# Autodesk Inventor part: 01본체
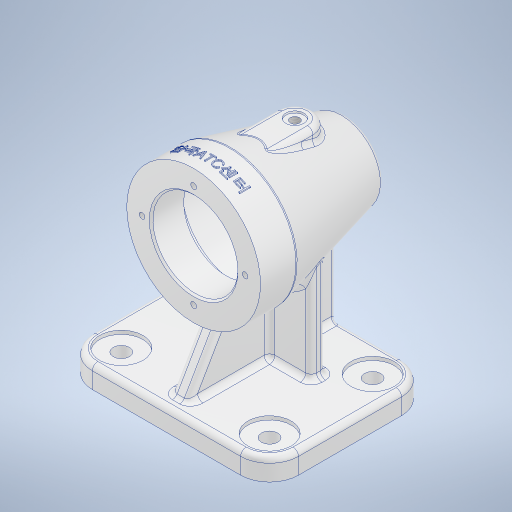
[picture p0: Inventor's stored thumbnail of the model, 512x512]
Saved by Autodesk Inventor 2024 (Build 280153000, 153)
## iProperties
Created: 2024-12
Part Number: 01본체
Material: 알루미늄 6061
Document SubType Name: Modeling
Designer: user
Density: 2.7 g/cm^3
Appearance: 알루미늄 - 평지
Mass: 740.131 g
Surface Area: 668.51 cm^2
Volume: 274.123 cm^3
Author: user
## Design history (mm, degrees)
sketch "스케치2"
  geometry: L1 (0, 56)-(0, -28); L2 (0, -28)-(21, -28); L3 (37, 36)-(37, 56); L4 (37, 56)-(0, 56); L5 (37, 36)-(21, -28); 1 further point
  constraints: 10 end point, 2 perpendicular, 1 horizontal, 1 vertical, 1 vertical alignment
  dimensions: "d5" = 84 distance of L1.start L1.end; "d7" = 20 distance of L3.start L3.end; "d8" = 42 diameter of L2.end L1; "d9" = 74 diameter of L3 L1; "d38" = 56 distance of point (0, 0) L1.start
revolve "회전1" sketch "스케치2" stored, may be unused: angle "d23" = 90 deg
fillet "모깎기1" dims "d24" = 3
node "작업 평면1"
sketch "스케치3"
  geometry: L1 (57, -18)-(-57, -18); L2 (-57, -18)-(-57, 71); L3 (-57, 71)-(57, 71); L4 (57, 71)-(57, -18); L5 (57, -18)-(-57, 71); L6 (-57, -18)-(57, 71); 2 further points
  constraints: 12 end point, 2 midpoint, 2 parallel, 1 horizontal, 1 perpendicular, 1 vertical alignment
  dimensions: "d29" = 71 distance from line of point (0, 0) L3; "d30" = 89 distance of L1.end L2.end; "d31" = 114 distance of L1.start L1.end
extrude "돌출2" join sketch "스케치3" distance "d32" = 12; taper "d33" = 0 deg
fillet "모깎기2" dims "d34" = 16
sketch "스케치4"
  geometry: L1 (41, 18)-(-41, 18) reference; L2 (-28, -11)-(28, -11); L3 (28, -11)-(28, -19); L4 (28, -19)-(-28, -19); L5 (-28, -19)-(-28, -11); L6 (-28, -11)-(28, -19); L7 (28, -11)-(-28, -19); 2 further points
  constraints: 12 end point, 2 midpoint, 2 parallel, 1 horizontal, 1 perpendicular, 1 vertical alignment
  dimensions: "d35" = 8 distance of L2.end L3.end; "d36" = 56 distance of L2.start L2.end; "d37" = 29 distance between parallel lines of L1 L2
extrude "돌출3" join sketch "스케치4" stored distance "d39" = 12; taper "d40" = 0 deg
sketch "스케치5"
  geometry: L1 (36.91, 35.642)-(21.568, -25.728) reference; L2 (18.658, -28)-(-18.658, -28) reference; L3 (-21.568, -25.728)-(-30.75, 11) reference; L4 (-30.75, 11)-(-70, 11) reference; L5 (-70, 11)-(-70, -18) reference; L6 (-70, -18)-(-82, -18) reference; L7 (-82, -18)-(-82, 71) reference; L8 (-82, 71)-(-70, 71) reference; L9 (-70, 71)-(-70, 19) reference; L10 (-70, 19)-(-32.75, 19) reference; L11 (-32.75, 19)-(-36.91, 35.642) reference; L12 (-37, 36.369)-(-37, 56) reference; L13 (-37, 56)-(37, 56) reference; L14 (37, 56)-(37, 36.369) reference; L15 (-70, 64)-(0, 23.585); L16 (0, 23.585)-(0, -18); L17 (36.91, 35.642)-(-36.91, 35.642) reference; L18 (0, -18)-(-70, -18); L19 (-70, 64)-(-70, -18); A1 r 3 centre (18.658, -25) between (18.658, -28) and (21.568, -25.728) reference; A2 r 3 centre (-18.658, -25) between (-21.568, -25.728) and (-18.658, -28) reference; A3 r 3 centre (-34, 36.369) between (-37, 36.369) and (-36.91, 35.642) reference; A4 r 3 centre (34, 36.369) between (36.91, 35.642) and (37, 36.369) reference; 1 further point
  constraints: 8 end point, 2 point on line, 1 collinear, 1 horizontal, 1 perpendicular
  dimensions: "d41" = 60 deg angle of L9 L15; "d42" = 7 distance of L15.start L8.end
extrude "돌출4" join sketch "스케치5" stored distance "d43" = 10; taper "d44" = 0 deg
node "작업 평면2"
sketch "스케치7"
  geometry: L1 (-10, 25.928)-(10, 25.928); L2 (10, 25.928)-(10, 0); L3 (10, 0)-(-10, 0); L4 (-10, 0)-(-10, 25.928); L5 (-16.733, 36.369)-(-16.733, 56) reference; L6 (-16.733, 56)-(16.733, 56) reference; L7 (16.733, 56)-(16.733, 36.369) reference; A1 r 10 centre (0, 0) between (-10, 0) and (10, 0); A2 r 10 centre (0, 0) between (10, 0) and (-10, 0); 3 further points
  constraints: 8 end point, 4 point on circle, 2 centre point, 2 parallel, 1 coincident, 1 horizontal, 1 midpoint, 1 perpendicular, 4 other
  dimensions: "d61" = 20 distance of L1.start L1.end
extrude "돌출5" join sketch "스케치7" distance "d63" = 8.509; taper "d64" = 0 deg
sketch "스케치6"
  geometry: L1 (-21.568, -25.728)-(-23.5, -18) reference; L2 (-23.5, -18)-(-82, -18) reference; L3 (-82, -18)-(-82, 71) reference; L4 (-82, 71)-(-70, 71) reference; L5 (-70, 71)-(-70, 64) reference; L6 (-70, 64)-(-37, 44.947) reference; L7 (-37, 44.947)-(-37, 56) reference; L8 (-37, 56)-(37, 56) reference; L9 (37, 56)-(37, 36.369) reference; L10 (36.91, 35.642)-(33, 20) reference; L11 (18.658, -28)-(-18.658, -28) reference; L12 (23.5, 56)-(23.5, 38); L13 (23.5, 38)-(25.942, 38); L14 (30.793, 31.787)-(21.664, -4.728); L15 (18.754, -7)-(17.5, -7); L16 (17.5, -7)-(17.5, -16.7); L17 (17.2, -17)-(15.5, -17); L18 (15.5, -17)-(15.5, -17); L19 (12.5, -20)-(0, -20); L20 (0, 56)-(0, -28); L21 (23.5, 56)-(0, 56); L22 (-37, 56)-(37, 56) reference; L23 (33, 20)-(33, -10) reference; L24 (33, -10)-(25.5, -10) reference; L25 (25.5, -10)-(21.568, -25.728) reference; A1 r 3 centre (34, 36.369) between (36.91, 35.642) and (37, 36.369) reference; A2 r 3 centre (18.658, -25) between (18.658, -28) and (21.568, -25.728) reference; A3 r 3 centre (-18.658, -25) between (-21.568, -25.728) and (-18.658, -28) reference; A4 r 5 centre (25.942, 33) between (30.793, 31.787) and (25.942, 38); A5 r 3 centre (18.754, -4) between (18.754, -7) and (21.664, -4.728); A6 r 3 centre (12.5, -17) between (12.5, -20) and (15.5, -17); A7 r 0.3 centre (17.2, -16.7) between (17.2, -17) and (17.5, -16.7); 7 further points
  constraints: 20 end point, 10 point on line, 8 point on circle, 8 tangent, 4 centre point, 3 midpoint, 3 perpendicular, 2 horizontal, 2 vertical, 1 collinear, 1 equal radius, 1 parallel
  dimensions: "d45" = 18 distance of L12.start L12.end; "d46" = 45 vertical distance of point (21.096, -7) point (32.346, 38); "d47" = 10 distance of L15.end point (17.5, -17); "d48" = 3 distance of L17.end point (15.5, -20); "d49" = 47 diameter of L12 L20; "d50" = 5 distance between parallel lines of L10 L14; "d51" = 35 diameter of L16 L20; "d52" = 31 diameter of point (15.5, -17) L20; "d53" = 5 radius of A4; "d54" = 3 radius of A5; "d55" = 0.3 radius of A7
revolve "회전2" sketch "스케치6" stored, may be unused: angle "d56" = 90 deg
chamfer "모따기2" distance "d57" = 1; stored, may be unused: second distance "d58" = 2, angle "d59" = 45 deg
sketch "스케치8"
  geometry: C1 r 5 at (0, 0); A1 r 10 centre (0, 0) between (10, 0) and (-10, 0) reference
  constraints: 1 centre point, 1 coincident
  dimensions: "d65" = 10 diameter of C1
extrude "돌출6" cut sketch "스케치8" distance "d66" = 1; taper "d67" = 0 deg
sketch "스케치9"
  geometry: C1 r 5 at (0, 0) reference
hole "구멍1" sketch "스케치9" at (0, 0) diameter "d68" = 5.1881; stored, may be unused: countersink angle "d72" = 90 deg, drill point angle "d74" = 118 deg; dims "d69" = 12, "d70" = 4, "d71" = 2, "d73" = 10.75
fillet "모깎기3" dims "d75" = 3
fillet "모깎기4" dims "d76" = 3
sketch "스케치11"
  geometry: A1 r 13 centre (-41, 2) between (-41, 15) and (-54, 2) reference; A2 r 13 centre (-41, -55) between (-54, -55) and (-41, -68) reference; A3 r 13 centre (41, -55) between (41, -68) and (54, -55) reference; A4 r 13 centre (41, 2) between (54, 2) and (41, 15) reference; 1 further point
hole "구멍2" sketch "스케치11" at (41, -55), (41, 2), (-41, 2), (-41, -55) diameter "d77" = 9; stored, may be unused: countersink angle "d81" = 90 deg, drill point angle "d83" = 118 deg; dims "d78" = 12, "d79" = 24, "d80" = 2, "d82" = 10.75
node "작업 평면3"
sketch "스케치12"
  geometry: L1 (37, -56)-(-37, -56) reference; 2 further points
  constraints: 1 vertical alignment, 1 other
  dimensions: "d85" = 9 distance from line of L1 point (0, -47)
feature "엠보싱1" sketch "스케치12" dims "d5" = 84, "d7" = 20, "d8" = 42, "d9" = 74, "d38" = 56, "d86" = 0.5, "d87" = 0
sketch "스케치13" dims "d88" = 57
  geometry: C1 r 37 at (0, 0) reference; C2 r 24.5 at (0, 0) reference; 2 further points
  constraints: 2 vertical alignment, 1 coincident, 2 other
hole "구멍3" sketch "스케치13" at (0, 28.5) diameter "d89" = 3.242; stored, may be unused: countersink angle "d93" = 90 deg, drill point angle "d95" = 118 deg; dims "d90" = 8, "d91" = 24, "d92" = 2, "d94" = 10
node "솔리드2"
pattern_circular "원형 패턴1" dims angle "d97" = 360 deg
node "절단 모서리 투영1"
node "절단 모서리 투영2"
node "절단 모서리 투영3"
feature "A9D066F2-1C7D-4E18-AEED-F7BC21143FA4" dims "d77" = 9, "d78" = 12, "d79" = 24, "d80" = 2, "d81" = 90 deg, "d82" = 10.75, "d83" = 118 deg
other parameters: "d28" = -82, "d60" = -115, "d84" = 115.5
